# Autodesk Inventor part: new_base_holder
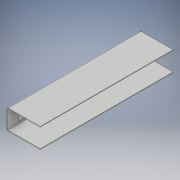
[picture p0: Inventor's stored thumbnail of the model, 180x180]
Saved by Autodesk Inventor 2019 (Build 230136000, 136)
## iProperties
Created: 2020-03
Part Number: new_base_holder
Material: Generic
Document SubType Name: Sheet Metal
Designer: ash
Density: 1 g/cm^3
Sheet Metal Rule: Default_mm
Appearance: Default
Author: ash
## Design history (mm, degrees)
node "Face1"
  sketch "Sketch1"
    geometry: L1 (0, 11.966)-(15, 11.966); L2 (15, 11.966)-(15, -88.034); L3 (15, -88.034)-(0, -88.034); L4 (0, -88.034)-(0, 11.966); 1 further point
    constraints: 8 end point, 2 parallel, 1 horizontal, 1 perpendicular
    dimensions: "d0" = 15 distance of L2.end L3.end; "d1" = 100 distance of L1.end L2.end
node "Flange1"
sketch "Sketch3"
  geometry: L1 (-56.184, 1.5)-(-79.584, 1.5); L2 (-79.584, 1.5)-(-79.584, 13.6); L3 (-79.584, 13.6)-(-56.184, 13.6); L4 (-56.184, 13.6)-(-56.184, 1.5); L5 (3.516, 1.5)-(-19.884, 1.5); L6 (-19.884, 1.5)-(-19.884, 13.6); L7 (-19.884, 13.6)-(3.516, 13.6); L8 (3.516, 13.6)-(3.516, 1.5); L9 (-88.034, 1)-(11.966, 1) reference; L10 (11.966, 1)-(11.966, 14) reference; L11 (-88.034, 14)-(-88.034, 1) reference; L12 (-88.034, 0.5)-(11.966, 0.5) reference; L13 (11.966, 14)-(-88.034, 14) reference; 1 further point
  constraints: 16 end point, 4 parallel, 2 horizontal, 2 perpendicular
  dimensions: "d13" = 23.4 distance of L2.end L3.end; "d14" = 12.1 distance of L1.end L2.end; "d15" = 23.4 distance of L6.end L7.end; "d16" = 12.1 distance of L5.end L6.end; "d17" = 0.5 distance between parallel lines of L5 L9; "d18" = 8.45 distance between parallel lines of L8 L10; "d19" = 8.45 distance between parallel lines of L11 L2; "d20" = 1 distance between parallel lines of L12 L1; "d21" = 0.4 distance between parallel lines of L13 L3 (derived)
extrude "Extrusion1" cut sketch "Sketch3" distance "d22" = 10; taper "d23" = 0 deg
sketch "Sketch4"
  geometry: 1 further point
body "Solid1"
face "Plate1" dims "d2" = 0.5 (= Thickness)
sketch "Sketch2"
  geometry: L1 through (0, -50) direction (0, 1); L2 through (-12.5, 0) direction (-1, 0); L3 (-25, 0)-(-25, -100); L4 (-25, -100)-(0, -100)
  constraints: 6 end point, 1 horizontal, 1 perpendicular, 1 vertical
face "Plate2" dims "d2" = 0.5 (= Thickness), "d3" = 0.5 (= BendReliefWidth), "d4" = 0.25 (= BendReliefDepth), "d5" = 1 (= MinimumRemnant), "d6" = 0.5 (= TransitionRadius), "d7" = 25, "d8" = 90 deg, "d9" = 0.5 (= BendRadius), "d10" = 2 (= CornerReliefSize), "d11" = 0.5 (= GapSize), "d12" = 0.5 (= JacobiRadiusSize), "SeamGap" = 0.01
bend "Bend1" dims "d2" = 0.5 (= Thickness), "d3" = 0.5 (= BendReliefWidth), "d4" = 0.25 (= BendReliefDepth), "d5" = 1 (= MinimumRemnant), "d6" = 0.5 (= TransitionRadius), "d7" = 25, "d8" = 90 deg, "d9" = 0.5 (= BendRadius), "SeamGap" = 0.01
feature "Corner1" dims "d7" = 25, "d8" = 90 deg, "d10" = 2 (= CornerReliefSize), "d11" = 0.5 (= GapSize), "d12" = 0.5 (= JacobiRadiusSize)
other parameters: "Thickness" = 0.5, "BendRadius" = 0.5 (= Thickness), "BendReliefWidth" = 0.5 (= Thickness), "BendReliefDepth" = 0.25 (= 0.5 x Thickness), "CornerReliefSize" = 2 (= 4 x Thickness), "MinimumRemnant" = 1 (= 2 x Thickness), "TransitionRadius" = 0.5 (= BendRadius), "JacobiRadiusSize" = 0.5 (= BendRadius), "GapSize" = 0.5 (= Thickness), "GapSize" = 0.5 (= Thickness), "Thickness" = 0.5 (derived), "MinimumRemnant" = 1 (= 2 x Thickness), "CornerReliefSize" = 2 (= 4 x Thickness), "BendReliefDepth" = 0.25 (= 0.5 x Thickness), "BendReliefWidth" = 0.5 (= Thickness), "BendRadius" = 0.5 (= Thickness), "JacobiRadiusSize" = 0.5 (= BendRadius), "TransitionRadius" = 0.5 (= BendRadius)
